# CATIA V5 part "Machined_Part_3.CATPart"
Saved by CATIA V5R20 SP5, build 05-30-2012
Part number: Machined_Part_3
Bounding box of the stored display mesh (mm): x -34.455 to 82.805, y -95.042 to 170.526, z 0 to 76.2
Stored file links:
  C:\Users\rsz0866\Documents\007_CATIA_STEP-Files_and_Test_Models\0001_Machined_Parts_Models\Machined_Part_3.CATPart
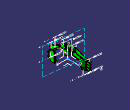
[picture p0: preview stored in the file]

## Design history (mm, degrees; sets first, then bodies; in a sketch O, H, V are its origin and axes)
AxisSystem1: origin (0, 0, 0), X (1, 0, 0), Y (0, 1, 0), Z (0, 0, 1)
AxisSystem2 "Axis System.2 ( *AXS1 - wsp *MASTER -  )": origin (0, 0, 0), X (1, 0, 0), Y (0, 1, 0), Z (0, 0, 1)
TTRSSet1
f4a2d38f3ddc11d3a929006094b99c4b_11 "CATTPSSet"
Set1
  Sketch1 "Top Sketch" on Plane12, origin (0, 0, 76.2), H (1, 0, 0), V (0, 1, 0)
    point P41 (38.3585, -78.4326)
    point P43 (38.3585, -78.4326)
    point P49 (-34.4551, -32.537)
    line L1 (77.9773, -17.6115) -> (82.8051, -65.2862)
    line L2 (45.9027, -87.2055) -> (51.7305, -93.9824)
    line L3 (37.3928, -77.3097) -> (13.1457, -49.1136)
    line L4 (6.9462, -45.7536) -> (-27.9108, -41.0986)
    line L5 (-8.3082, 163.2539) -> (-34.4551, -32.537)
    point P65 (-34.4551, -32.537)
    line L6 (3.5734, 151.0017) -> (3.0896, 147.3794)
    line L7 (8.4368, 108.2691) -> (1.2721, 54.6193)
    line L8 (53.3982, -33.8045) -> (32.3321, -30.9912)
    point P66 (53.3982, -33.8045)
    line L9 (53.6147, -32.2958) -> (53.3982, -33.8045)
    line L10 (43.6543, -82.0898) -> (45.4804, -86.5178)
    arc A1 centre (47.8285, -85.5494) radius 2.54 from (45.4804, -86.5178) to (45.9027, -87.2055) ccw
    arc A2 centre (0, 162.1444) radius 8.382 from (8.3082, 161.0349) to (-8.3082, 163.2539) ccw
    arc A3 centre (0, 162.1444) radius 8.382 from (6.1381, 156.4364) to (8.3082, 161.0349) ccw
    arc A4 centre (13.3922, 149.6905) radius 9.906 from (6.1381, 156.4364) to (3.5734, 151.0017) ccw
    arc A5 centre (12.908, 146.0685) radius 9.9055 from (3.0896, 147.3794) to (3.9015, 141.9453) ccw
    arc A6 centre (12.9085, 146.0686) radius 9.906 from (3.9015, 141.9453) to (11.4699, 136.2676) ccw
    arc A7 centre (10.0681, 126.7179) radius 9.652 from (14.2492, 118.0186) to (13.094, 135.8834) ccw
    arc A8 centre (10.0681, 126.7179) radius 9.652 from (13.094, 135.8834) to (11.4699, 136.2676) ccw
    arc A9 centre (18.5404, 109.0903) radius 9.906 from (14.2492, 118.0186) to (9.5986, 113.3534) ccw
    arc A10 centre (18.5396, 109.0905) radius 9.9052 from (9.5986, 113.3534) to (8.7216, 110.4015) ccw
    line L11 (8.7216, 110.4015) -> (8.4368, 108.2691)
    arc A11 centre (11.091, 53.308) radius 9.906 from (1.2721, 54.6193) to (2.0839, 49.1847) ccw
    arc A12 centre (11.091, 53.308) radius 9.906 from (2.0839, 49.1847) to (8.555, 43.7321) ccw
    arc A13 centre (6.9294, 37.5937) radius 6.35 from (12.9966, 35.7199) to (8.555, 43.7321) ccw
    arc A14 centre (22.4615, 32.7967) radius 9.906 from (12.9966, 35.7199) to (13.6686, 28.2344) ccw
    arc A15 centre (22.4611, 32.7964) radius 9.9055 from (13.6686, 28.2344) to (16.8641, 24.6237) ccw
    arc A16 centre (0, 0) radius 29.845 from (25.2594, -15.8962) to (16.8641, 24.6237) ccw
    arc A17 centre (33.6433, -21.1723) radius 9.906 from (25.2594, -15.8962) to (32.3321, -30.9912) ccw
    arc A18 centre (79.7726, -65.5933) radius 3.048 from (79.2019, -68.5874) to (82.8051, -65.2862) ccw
    arc A19 centre (75.6351, -87.3005) radius 19.05 from (79.2019, -68.5874) to (57.0199, -91.3476) ccw
    arc A20 centre (54.0415, -91.9951) radius 3.048 from (51.7305, -93.9824) to (57.0199, -91.3476) ccw
    construction arc A21 centre (47.9877, -70.152) radius 12.7 from (38.3585, -78.4326) to (46.7838, -82.7948) ccw
    arc A22 centre (47.9877, -70.152) radius 12.7 from (38.3585, -78.4326) to (43.6543, -82.0898) ccw
    line L12 (38.3585, -78.4326) -> (37.3928, -77.3097)
    arc A23 centre (5.6352, -55.5721) radius 9.9056 from (13.1457, -49.1136) to (8.548, -46.1045) ccw
    arc A24 centre (5.6349, -55.5724) radius 9.906 from (8.548, -46.1045) to (6.9462, -45.7536) ccw
    arc A25 centre (-26.9022, -33.5457) radius 7.62 from (-34.4551, -32.537) to (-27.9108, -41.0986) ccw
    line L13 (53.6147, -32.2958) -> (54.0504, -29.2591)
    line L14 (54.2639, -27.7708) -> (54.0504, -29.2591)
    line L15 (54.2639, -27.7708) -> (60.1112, -16.8496)
    arc A26 centre (64.3366, -25.5275) radius 9.652 from (65.6142, -15.9605) to (60.1112, -16.8496) ccw
    line L16 (74.3541, -17.1276) -> (65.6142, -15.9605)
    line L17 (74.3541, -17.1276) -> (75.9069, -17.335)
    line L18 (75.9069, -17.335) -> (77.9773, -17.6115)
    construction line L19 (39.3447, -71.6399) -> (45.4804, -86.5178)
    radius A1 = 2.54
    tangency: L1 A18, L2 A20, L3 A20, L4 A25, L5 A2, L6 A4, L7 A11, L8 A17, A1 L10, A1 L2
    coincidence: P66 L13, L10 L19, P41 P43, P49 P65
    parallelism: L9 L13
  Sketch2 "Cut 1 Sketch" on Plane13, origin (0, 0, 5.08), H (1, 0, 0), V (0, 1, 0)
    point P2 (4.1097, 119.1239)
    point P4 (4.1097, 119.1239)
    line L1 (3.0897, 147.3797) -> (0.52, 128.1375)
    line L2 (3.0897, 147.3797) -> (33.2265, 145.3887)
    line L3 (31.6407, 108.2613) -> (8.4357, 108.2613)
    line L4 (33.2265, 145.3887) -> (31.6407, 108.2613)
    construction arc A1 centre (-3.3972, 109.8415) radius 11.938 from (8.4357, 108.2613) to (4.1097, 119.1239) ccw
    arc A2 centre (-3.3972, 109.8415) radius 11.938 from (8.4357, 108.2613) to (4.1097, 119.1239) ccw
    arc A3 centre (10.3388, 126.8263) radius 9.906 from (0.52, 128.1375) to (4.1097, 119.1239) ccw
    coincidence: P2 P4
    horizontal: L3 H
  Sketch3 "Cut 2 Sketch" on Plane17, origin (0, 0, 67.3735), H (1, 0, 0), V (0, 1, 0)
    arc A1 centre (11.0905, 53.3079) radius 9.9056 from (1.2721, 54.6193) to (2.0839, 49.1847) ccw
    arc A2 centre (11.091, 53.308) radius 9.906 from (2.0839, 49.1847) to (8.555, 43.7321) ccw
    arc A3 centre (6.9294, 37.5937) radius 6.35 from (12.9966, 35.7199) to (8.555, 43.7321) ccw
    arc A4 centre (22.4615, 32.7967) radius 9.906 from (12.9966, 35.7199) to (13.6686, 28.2344) ccw
    arc A5 centre (22.4611, 32.7964) radius 9.9055 from (13.6686, 28.2344) to (16.8641, 24.6237) ccw
    arc A6 centre (0, 0) radius 29.845 from (16.8641, 24.6237) to (6.861, 29.0457) ccw
    arc A7 centre (9.1383, 38.6863) radius 9.906 from (-0.6805, 39.9976) to (5.9121, 29.3204) ccw
    line L1 (1.2721, 54.6193) -> (-0.6805, 39.9976)
    arc A8 centre (9.1383, 38.6863) radius 9.906 from (5.9121, 29.3204) to (6.861, 29.0457) ccw
  Sketch4 "Pocket 1 Sketch" on Plane11, origin (0, 0, 59.4614), H (1, 0, 0), V (0, 1, 0)
    point P4 (-3.2329, 36.236)
    point P7 (-22.8706, 38.8585)
    line L1 (-13.216, 111.1528) -> (-22.8706, 38.8585)
    point P9 (-22.8706, 38.8585)
    line L2 (6.4216, 108.5303) -> (-3.2329, 36.236)
    point P10 (-3.2329, 36.236)
    arc A1 centre (-3.3972, 109.8415) radius 9.906 from (6.4216, 108.5303) to (-13.216, 111.1528) ccw
    arc A2 centre (-13.0517, 37.5472) radius 9.906 from (-5.7297, 30.8751) to (-3.2329, 36.236) ccw
    arc A3 centre (-13.0517, 37.5472) radius 9.906 from (-21.868, 33.0303) to (-5.7297, 30.8751) ccw
    arc A4 centre (-13.0517, 37.5472) radius 9.906 from (-22.8706, 38.8585) to (-21.868, 33.0303) ccw
    coincidence: P9 A4, P4 P10, P7 P9
    tangency: L1 A2, L2 A1
  Sketch5 "Step 1 Sketch" on Plane20, origin (0, 0, 67.3735), H (1, 0, 0), V (0, 1, 0)
    arc A1 centre (5.6352, -55.5721) radius 9.9056 from (13.1457, -49.1136) to (8.548, -46.1045) ccw
    line L1 (13.1457, -49.1136) -> (6.9025, -41.8536)
    line L2 (-1.3126, -32.3005) -> (6.9025, -41.8536)
    arc A2 centre (-8.8234, -38.7594) radius 9.906 from (-1.3126, -32.3005) to (-6.6246, -29.1005) ccw
    arc A3 centre (0, 0) radius 29.845 from (-10.6775, -27.8696) to (-6.6246, -29.1005) ccw
    line L3 (-10.6775, -27.8696) -> (-22.6141, -23.2964)
    arc A4 centre (-26.1581, -32.5468) radius 9.906 from (-22.6141, -23.2964) to (-24.8468, -22.7279) ccw
    line L4 (-24.8468, -22.7279) -> (-30.4821, -21.9754)
    arc A5 centre (-30.1459, -19.4577) radius 2.54 from (-32.6635, -19.1215) to (-30.4821, -21.9754) ccw
    line L5 (-33.0835, -22.266) -> (-32.6635, -19.1215)
    line L6 (-34.4551, -32.537) -> (-33.0835, -22.266)
    arc A6 centre (-26.9022, -33.5457) radius 7.62 from (-34.4551, -32.537) to (-27.9108, -41.0986) ccw
    line L7 (-19.0026, -42.2883) -> (-27.9108, -41.0986)
    line L8 (-19.0026, -42.2883) -> (-17.492, -42.49)
    line L9 (6.9462, -45.7536) -> (-17.492, -42.49)
    arc A7 centre (5.6349, -55.5724) radius 9.906 from (8.548, -46.1045) to (6.9462, -45.7536) ccw
  Sketch6 "Cut 3 Sketch" on Plane26, origin (0, 0, 6.858), H (1, 0, 0), V (0, 1, 0)
    line L1 (-19.0026, -42.2883) -> (-27.9108, -41.0986)
    arc A1 centre (-26.9022, -33.5457) radius 7.62 from (-34.4551, -32.537) to (-27.9108, -41.0986) ccw
    line L2 (-34.4551, -32.537) -> (-33.0835, -22.266)
    line L3 (-33.0835, -22.266) -> (-32.6635, -19.1215)
    arc A2 centre (-30.1459, -19.4577) radius 2.54 from (-32.6635, -19.1215) to (-30.4821, -21.9754) ccw
    line L4 (-24.8468, -22.7279) -> (-30.4821, -21.9754)
    arc A3 centre (-26.1581, -32.5468) radius 9.906 from (-22.6141, -23.2964) to (-24.8468, -22.7279) ccw
    arc A4 centre (-26.1576, -32.5461) radius 9.9052 from (-18.2294, -26.6083) to (-22.6141, -23.2964) ccw
    arc A5 centre (-26.1581, -32.5468) radius 9.906 from (-16.3393, -33.858) to (-18.2294, -26.6083) ccw
    line L5 (-17.492, -42.49) -> (-16.3393, -33.858)
    line L6 (-19.0026, -42.2883) -> (-17.492, -42.49)
  Sketch7 "Step 2 Sketch" on Plane22, origin (0, 0, 67.3735), H (1, 0, 0), V (0, 1, 0)
    line L1 (78.9049, -46.9405) -> (83.4372, -91.6975)
    line L2 (14.7318, -48.1756) -> (63.5889, -104.4908)
    line L3 (63.5889, -104.4908) -> (83.4372, -91.6975)
    arc A1 centre (69.0493, -47.9386) radius 9.906 from (78.9049, -46.9405) to (70.3606, -38.1197) ccw
    line L4 (23.5256, -31.8652) -> (70.3606, -38.1197)
    arc A2 centre (22.2143, -41.684) radius 9.906 from (23.5256, -31.8652) to (15.7227, -34.2015) ccw
    arc A3 centre (22.2143, -41.684) radius 9.906 from (15.7228, -34.2014) to (14.7318, -48.1756) ccw
    tangency: L1 A1, L2 A3
  Sketch8 "Cut 4 Sketch" on Plane18, origin (0, 0, 5.08), H (1, 0, 0), V (0, 1, 0)
    point P1 (65.4758, -35.4173)
    point P15 (53.6147, -32.2958)
    point P17 (53.6147, -32.2958)
    point P20 (65.4758, -35.4173)
    arc A1 centre (66.787, -25.5985) radius 9.906 from (65.4758, -35.4173) to (76.6426, -24.6005) ccw
    line L1 (76.6426, -24.6005) -> (75.9069, -17.335)
    line L2 (74.3541, -17.1276) -> (65.6142, -15.9605)
    arc A2 centre (64.3366, -25.5275) radius 9.652 from (65.6142, -15.9605) to (60.1112, -16.8496) ccw
    line L3 (54.2639, -27.7708) -> (60.1112, -16.8496)
    line L4 (74.3541, -17.1276) -> (75.9069, -17.335)
    line L5 (54.2639, -27.7708) -> (54.0504, -29.2591)
    line L6 (53.6147, -32.2958) -> (54.0504, -29.2591)
    construction line L7 (53.6147, -32.2958) -> (53.3982, -33.8045)
    line L8 (53.6147, -32.2958) -> (53.3982, -33.8045)
    construction line L9 (52.5433, -33.6903) -> (65.4758, -35.4173)
    line L10 (53.3982, -33.8045) -> (65.4758, -35.4173)
    coincidence: P1 P20, P15 P17
  Sketch9 "Side 1 Sketch" on Plane14, origin (-29.5824, 3.9506, 0), H (-0.1324, -0.9912, 0), V (0, 0, 1)
    point P8 (18.4332, 0)
    point P17 (18.4332, 0)
    line L1 (18.4332, 0) -> (18.4332, -23.6301)
    line L2 (18.4332, -23.6301) -> (-108.4253, -23.6301)
    line L3 (-108.4253, -23.6301) -> (-108.4253, 0)
    arc A1 centre (5.7049, 53.8766) radius 2.286 from (7.9494, 54.3099) to (5.7049, 56.1626) ccw
    line L4 (5.7049, 56.1626) -> (-9.5351, 56.1626)
    arc A2 centre (-9.5351, 53.8766) radius 2.286 from (-9.5351, 56.1626) to (-11.1593, 55.4853) ccw
    line L5 (7.9494, 54.3099) -> (18.4332, 0)
    line L6 (-11.1593, 55.4853) -> (-26.0895, 40.4114)
    line L7 (-26.0895, 40.4114) -> (-83.7739, 40.4114)
    arc A3 centre (-83.7739, 38.1254) radius 2.286 from (-83.7739, 40.4114) to (-85.7536, 39.2684) ccw
    line L8 (-108.4253, 0) -> (-85.7536, 39.2684)
    coincidence: P17 H, P8 P17
    vertical: L1 V, L3 V
    horizontal: L2 H
  Sketch10 "Cut 5 Sketch" on Plane14, origin (-29.5824, 3.9506, 0), H (-0.1324, -0.9912, 0), V (0, 0, 1)
    line L1 (-135.0636, 56.1594) -> (-183.8689, 56.1594)
    line L2 (-135.0636, 42.4434) -> (-183.8689, 42.4434)
    line L3 (-135.0636, 25.4254) -> (-185.0407, 25.4254)
    line L4 (-135.0636, 22.1234) -> (-185.6717, 22.1234)
    line L5 (-135.0636, 8.4074) -> (-185.6717, 8.4074)
    line L6 (-146.4936, 5.1054) -> (-185.0407, 5.1054)
    line L7 (-144.9696, 0) -> (-185.0407, 0)
    line L8 (-183.8689, 56.1594) -> (-183.8689, 42.4434)
    line L9 (-135.0636, 39.1414) -> (-185.0407, 39.1414)
    line L10 (-185.0407, 39.1414) -> (-185.0407, 25.4254)
    line L11 (-185.6717, 8.4074) -> (-185.6717, 22.1234)
    line L12 (-185.0407, 5.1054) -> (-185.0407, 0)
    arc A1 centre (-135.0636, 54.6354) radius 1.524 from (-133.5396, 54.6354) to (-135.0636, 56.1594) ccw
    arc A2 centre (-135.0636, 43.9674) radius 1.524 from (-135.0636, 42.4434) to (-133.5396, 43.9674) ccw
    line L13 (-133.5396, 43.9674) -> (-133.5396, 54.6354)
    arc A3 centre (-135.0636, 37.6174) radius 1.524 from (-133.5396, 37.6174) to (-135.0636, 39.1414) ccw
    line L14 (-133.5396, 26.9494) -> (-133.5396, 37.6174)
    arc A4 centre (-135.0636, 26.9494) radius 1.524 from (-135.0636, 25.4254) to (-133.5396, 26.9494) ccw
    arc A5 centre (-135.0636, 20.5994) radius 1.524 from (-133.5396, 20.5994) to (-135.0636, 22.1234) ccw
    line L15 (-133.5396, 9.9314) -> (-133.5396, 20.5994)
    arc A6 centre (-135.0636, 9.9314) radius 1.524 from (-135.0636, 8.4074) to (-133.5396, 9.9314) ccw
    arc A7 centre (-146.4936, 3.5814) radius 1.524 from (-144.9696, 3.5814) to (-146.4936, 5.1054) ccw
    line L16 (-144.9696, 0) -> (-144.9696, 3.5814)
    tangency: L1 A1, L2 A2, L3 A4, L4 A5, L5 A6, L6 A7, L9 A3
    horizontal: L7 H
    vertical: L8 V, L10 V, L11 V, L12 V
  Sketch11 "Bump Sketch" on Plane15, origin (0, 0, 60.7314), H (1, 0, 0), V (0, 1, 0)
    line L1 (2.2134, 150.8948) -> (3.5355, 150.7183)
    line L2 (3.5355, 150.7183) -> (1.8544, 138.13)
    line L3 (1.8544, 138.13) -> (0.5323, 138.3066)
    line L4 (0.5323, 138.3066) -> (2.2134, 150.8948)
  Sketch12 "Cut 6 Sketch" on Plane14, origin (-29.5824, 3.9506, 0), H (-0.1324, -0.9912, 0), V (0, 0, 1)
    line L1 (-17.0582, 79.0477) -> (-104.731, 59.5221)
    line L2 (-105.2832, 59.4614) -> (-175.7026, 59.4614)
    line L3 (-175.7026, 59.4614) -> (-175.7026, 79.0477)
    line L4 (-17.0582, 79.0477) -> (-175.7026, 79.0477)
    arc A1 centre (-105.2832, 62.0014) radius 2.54 from (-104.731, 59.5221) to (-105.2832, 59.4614) cw
    construction line L5 (-29.845, 76.2) -> (-104.7583, 59.5161)
    construction line L6 (-105.2553, 59.4614) -> (-160.7176, 59.4614)
    radius A1 = 2.54
    horizontal: L2 H, L4 H
    vertical: L3 V
    coincidence: L5 L1, L6 L2
    tangency: A1 L1, A1 L2
  Sketch13 "Cut 7 Sketch" on Plane1, origin (79.0424, -10.5557, 0), H (0.1324, 0.9912, 0), V (0, 0, 1)
    line L1 (-27.499, 76.8669) -> (-40.6805, 67.8193)
    line L2 (-42.1179, 67.3735) -> (-64.6036, 67.3735)
    line L3 (-64.6036, 67.3735) -> (-64.6036, 76.8669)
    line L4 (-64.6036, 76.8669) -> (-27.499, 76.8669)
    arc A1 centre (-42.1179, 69.9135) radius 2.54 from (-40.6805, 67.8193) to (-42.1179, 67.3735) cw
    construction line L5 (-40.7455, 67.7748) -> (-28.4707, 76.2)
    construction line L6 (-50.6037, 67.3735) -> (-54.4936, 67.3735)
    radius A1 = 2.54
    horizontal: L2 H, L4 H
    vertical: L3 V
    coincidence: L1 L5, L2 L6
    tangency: A1 L1, A1 L2
  Sketch14 "Cut 8 Sketch" on Plane22, origin (0, 0, 67.3735), H (1, 0, 0), V (0, 1, 0)
    line L1 (81.7555, -54.9213) -> (100.4309, -60.408)
    line L2 (100.4309, -60.408) -> (51.4529, -106.5897)
    line L3 (51.4529, -106.5897) -> (38.3585, -78.4326)
    arc A1 centre (79.6916, -64.6396) radius 9.906 from (81.0029, -54.8208) to (78.1741, -54.8505) ccw
    arc A2 centre (79.6916, -64.6396) radius 9.906 from (78.1741, -54.8505) to (70.6949, -60.4939) ccw
    arc A3 centre (64.9277, -57.8364) radius 6.35 from (66.8132, -63.9) to (70.6949, -60.4939) ccw
    arc A4 centre (72.4698, -82.0908) radius 19.05 from (66.8132, -63.9) to (53.8878, -77.8941) ccw
    arc A5 centre (47.6938, -76.4952) radius 6.35 from (47.4, -82.8384) to (53.8878, -77.8941) ccw
    arc A6 centre (47.9877, -70.152) radius 12.7 from (46.7838, -82.7948) to (47.4, -82.8384) ccw
    arc A7 centre (47.9877, -70.152) radius 12.7 from (38.3585, -78.4326) to (46.7838, -82.7948) ccw
    line L4 (81.0029, -54.8208) -> (81.7555, -54.9213)
    tangency: L1 A1
  Sketch15 "Cut 9 Sketch" on Plane19, origin (0, 0, 24.4475), H (1, 0, 0), V (0, -1, 0)
    line L1 (25.2038, 73.626) -> (25.2038, 24.2643)
    line L2 (51.4054, 47.6939) -> (54.641, 24.2643)
    line L3 (54.641, 24.2643) -> (25.2038, 24.2643)
    line L4 (48.0914, 53.7696) -> (25.2038, 73.626)
    arc A1 centre (41.5998, 46.2871) radius 9.906 from (50.6156, 50.3913) to (48.0914, 53.7696) ccw
    arc A2 centre (41.6087, 46.2901) radius 9.8967 from (51.2246, 48.6307) to (50.6156, 50.3913) ccw
    arc A3 centre (41.5998, 46.2871) radius 9.906 from (51.4054, 47.6939) to (51.2246, 48.6307) ccw
    vertical: L1 V
    tangency: L2 A2, L4 A1
    horizontal: L3 H
  Sketch16 "Cut 10 Sketch" on Plane19, origin (0, 0, 24.4475), H (1, 0, 0), V (0, -1, 0)
    point P4 (55.098, 66.7637)
    point P12 (53.2843, 48.9058)
    point P13 (53.3376, 48.5343)
    line L1 (41.8105, 63.5221) -> (41.3894, 64.0584)
    line L2 (55.098, 66.7637) -> (60.2297, 72.3813)
    point P28 (55.098, 66.7637)
    line L3 (55.7365, 64.4498) -> (61.7651, 71.0493)
    line L4 (78.9049, 46.9405) -> (80.0245, 57.9963)
    line L5 (36.6639, 58.6116) -> (10.6615, 84.8174)
    line L6 (10.6615, 84.8174) -> (55.7365, 100.8474)
    line L7 (55.7365, 100.8474) -> (103.6523, 61.1517)
    line L8 (53.3376, 48.5343) -> (53.2843, 48.9058)
    point P36 (53.3376, 48.5343)
    arc A1 centre (45.7214, 75.3292) radius 12.7 from (42.5224, 63.0387) to (48.9088, 63.0357) ccw
    arc A2 centre (45.7214, 75.3292) radius 12.7 from (48.9088, 63.0357) to (55.098, 66.7637) ccw
    arc A3 centre (65.1131, 55.8843) radius 12.7 from (55.7365, 64.4498) to (52.9481, 59.5314) ccw
    arc A4 centre (65.1131, 55.8843) radius 12.7 from (52.9481, 59.5314) to (52.5419, 54.0806) ccw
    line L9 (52.5419, 54.0806) -> (53.025, 50.713)
    line L10 (53.025, 50.713) -> (53.2843, 48.9058)
    arc A5 centre (65.9089, 50.338) radius 12.7 from (53.3376, 48.5343) to (67.59, 37.7497) ccw
    line L11 (67.59, 37.7497) -> (70.3606, 38.1197)
    arc A6 centre (69.0493, 47.9386) radius 9.906 from (70.3606, 38.1197) to (78.9049, 46.9405) ccw
    frozenspline C1
    construction line L12 through (-8.0936, 7.0217) direction (-0.6553, -0.7554)
    line L13 (41.3894, 64.0584) -> (36.6639, 58.6116)
    construction line L14 through (61.6936, 71.1113) direction (0.7554, -0.6553)
    line L15 (60.2297, 72.3813) -> (61.7651, 71.0493)
    construction line L16 through (-6.2072, 46.4806) direction (-0.9912, -0.1324)
    line L17 (103.6523, 61.1517) -> (80.0245, 57.9963)
    coincidence: L1 P12, P28 A2, P36 A5, P36 L10, P4 P28, P13 P36
    tangency: L2 A1, L3 A3, L4 A6, L8 A5
  Sketch17 "Cut 11 Sketch" on Plane6, origin (83.9556, -11.2118, 0), H (0.1324, 0.9912, 0), V (0, 0, 1)
    line L1 (-46.2073, 23.5372) -> (-23.2619, -6.9123)
    point P3 (-23.2619, -6.9123)
    line L2 (-48.033, 24.4475) -> (-70.3017, 24.4475)
    line L3 (-23.2619, -6.9123) -> (-70.3017, -6.9123)
    point P5 (-23.2619, -6.9123)
    line L4 (-70.3017, -6.9123) -> (-70.3017, 24.4475)
    arc A1 centre (-48.033, 22.1615) radius 2.286 from (-46.2073, 23.5372) to (-48.033, 24.4475) ccw
    tangency: L1 A1, L2 A1
    coincidence: P5 L1, P3 P5
    horizontal: L3 H
    vertical: L4 V
  Sketch18 on Plane6, origin (83.9556, -11.2118, 0), H (0.1324, 0.9912, 0), V (0, 0, 1)
    line L1 (-41.4222, 17.1872) -> (-25.7258, -3.6425)
    point P3 (-25.7258, -3.6425)
    line L2 (-43.2479, 18.0975) -> (-68.5047, 18.0975)
    line L3 (-68.5047, -3.6425) -> (-25.7258, -3.6425)
    point P5 (-25.7258, -3.6425)
    line L4 (-68.5047, -3.6425) -> (-68.5047, 18.0975)
    arc A1 centre (-43.2479, 15.8115) radius 2.286 from (-41.4222, 17.1872) to (-43.2479, 18.0975) ccw
    tangency: L1 A1, L2 A1
    coincidence: P5 L1, P3 P5
    vertical: L4 V
  Sketch19 on Plane7, origin (49.7371, -57.3295, 0), H (0.7554, 0.6553, 0), V (0, 0, 1)
    point P1 (-10.0454, 23.7779)
    line L1 (-10.0454, 23.7779) -> (-1.6921, 15.4247)
    point P3 (-10.0454, 23.7779)
    line L2 (-1.6921, 15.4247) -> (-17.8508, 15.4247)
    line L3 (-17.8508, 24.4475) -> (-11.6619, 24.4475)
    line L4 (-17.8508, 24.4475) -> (-17.8508, 15.4247)
    arc A1 centre (-11.6619, 22.1615) radius 2.286 from (-10.0454, 23.7779) to (-11.6619, 24.4475) ccw
    coincidence: P3 A1, P1 P3
    tangency: L1 A1, L3 A1
    horizontal: L2 H
    vertical: L4 V
  Sketch20 on Plane8, origin (-1.2775, -1.1083, 0), H (-0.6553, 0.7554, 0), V (0, 0, 1)
    line L1 (-110.9211, 24.4475) -> (-94.1431, 24.4475)
    line L2 (-94.1431, 24.4475) -> (-75.1591, 16.1212)
    line L3 (-75.1591, 16.1212) -> (-110.9211, 16.1212)
    line L4 (-110.9211, 16.1212) -> (-110.9211, 24.4475)
    construction line L5 (-104.8899, 24.4475) -> (-95.9518, 24.4475)
    construction line L6 (-90.6684, 22.9235) -> (-86.5369, 21.1115)
    horizontal: L1 H, L3 H
    vertical: L4 V
    coincidence: L1 L5, L2 L6
  Sketch21 on Plane9, origin (-16.7791, -14.5569, 0), H (0.6553, -0.7554, 0), V (0, 0, 1)
    line L1 (82.9003, 67.3735) -> (118.8045, 67.3735)
    line L2 (82.4744, 67.4135) -> (22.7115, 78.7459)
    line L3 (118.8045, 67.3735) -> (118.8045, 78.7459)
    line L4 (118.8045, 78.7459) -> (22.7115, 78.7459)
    arc A1 centre (82.9003, 69.6595) radius 2.286 from (82.4744, 67.4135) to (82.9003, 67.3735) ccw
    tangency: L1 A1, L2 A1
    vertical: L3 V
    horizontal: L4 H
  Sketch22 on Plane16, origin (0, 0, 40.4114), H (1, 0, 0), V (0, -1, 0)
    line L1 (6.4216, -108.5303) -> (2.3867, -78.3161)
    line L2 (-13.216, -111.1528) -> (-17.1757, -81.5021)
    line L3 (-17.1757, -81.5021) -> (2.3867, -78.3161)
    arc A1 centre (-3.3972, -109.8415) radius 9.906 from (-13.216, -111.1528) to (6.4216, -108.5303) ccw
    tangency: L1 A1, L2 A1
  Sketch23 on Plane21, origin (0, 0, 65.3415), H (1, 0, 0), V (0, -1, 0)
    line L1 (52.5433, 33.6903) -> (64.5759, -46.1654)
    line L2 (1.2721, -54.6193) -> (64.5759, -46.1654)
    line L3 (45.4804, 86.5178) -> (-15.4779, 42.759)
    line L4 (1.2721, -54.6193) -> (-1.2188, -35.967)
    arc A1 centre (-13.0517, -37.5472) radius 11.938 from (-1.2188, -35.967) to (-7.0013, -27.2561) ccw
    arc A2 centre (-13.0517, -37.5472) radius 11.938 from (-7.0013, -27.2561) to (-9.132, -26.2711) ccw
    arc A3 centre (0, 0) radius 27.813 from (-23.7748, -14.4334) to (-9.132, -26.2711) ccw
    arc A4 centre (-0.0731, -0.0413) radius 27.7291 from (-24.6354, -12.9097) to (-23.7748, -14.4334) ccw
    arc A5 centre (0, 0) radius 27.813 from (-27.5683, -3.6816) to (-24.6354, -12.9097) ccw
    line L5 (-28.3234, 1.9731) -> (-27.5683, -3.6816)
    line L6 (-28.6205, 4.1979) -> (-28.3234, 1.9731)
    line L7 (-28.6205, 4.1979) -> (-28.919, 6.4329)
    arc A6 centre (-19.1002, 7.7442) radius 9.906 from (-25.6558, 15.1707) to (-28.919, 6.4329) ccw
    line L8 (-17.2201, 21.8411) -> (-25.2333, 15.5232)
    arc A7 centre (0, 0) radius 27.813 from (-14.4704, 23.7523) to (-17.2201, 21.8411) ccw
    arc A8 centre (-15.7919, 25.9214) radius 2.54 from (-14.4704, 23.7523) to (-13.2742, 26.2577) ccw
    line L9 (-13.2742, 26.2577) -> (-15.4779, 42.759)
    arc A9 centre (41.4788, 27.4553) radius 12.7003 from (52.5433, 33.6903) to (51.6851, 35.0137) ccw
    arc A10 centre (41.4791, 27.4554) radius 12.7 from (51.6851, 35.0137) to (44.8545, 39.6987) ccw
    arc A11 centre (46.8798, 47.0446) radius 7.62 from (39.3268, 46.0359) to (44.8545, 39.6987) ccw
    line L10 (39.3268, 46.0359) -> (37.6498, 58.5938)
    arc A12 centre (62.8263, 61.956) radius 25.4 from (37.9834, 67.2467) to (37.4447, 60.9887) ccw
    arc A13 centre (62.8263, 61.956) radius 25.4 from (37.4447, 60.9887) to (37.6498, 58.5938) ccw
    arc A14 centre (62.8263, 61.956) radius 25.4 from (39.3447, 71.6399) to (37.9834, 67.2467) ccw
    line L11 (45.4804, 86.5178) -> (39.3447, 71.6399)
    perpendicularity: L2 L4
  Sketch24 on Plane34, origin (90.0787, 7.4041, 0), H (0.1324, 0.9912, 0), V (0, 0, 1)
    point P2 (-62.8786, 41.9735)
    point P3 (-62.8786, 41.9735)
    line L1 (-62.8786, 26.4795) -> (-103.3566, 26.4795)
    line L2 (-103.3566, 26.4795) -> (-103.3566, 65.3415)
    line L3 (-103.3566, 65.3415) -> (-62.8786, 65.3415)
    construction line L4 (-62.8786, 67.3735) -> (-62.8786, 41.9735)
    line L5 (-62.8786, 65.3415) -> (-62.8786, 41.9735)
    construction line L6 (-62.8786, 41.9735) -> (-62.8786, 28.0035)
    line L7 (-62.8786, 41.9735) -> (-62.8786, 26.4795)
    construction line L8 (-89.3381, 65.3415) -> (-73.7562, 65.3415)
    horizontal: L1 H, L3 H
    vertical: L2 V
    coincidence: L3 L8, P2 P3
  Sketch25 on Plane23, origin (-3.4997, -26.206, 0), H (-0.9912, 0.1324, 0), V (0, 0, 1)
    line L1 (-60.5746, 65.3415) -> (-38.49, 65.3417)
    line L2 (-38.49, 65.3417) -> (-38.49, 26.4794)
    line L3 (-38.49, 26.4794) -> (-60.5746, 26.4794)
    arc A1 centre (-60.5746, 36.3854) radius 9.906 from (-69.5878, 32.2755) to (-60.5746, 26.4794) ccw
    arc A2 centre (-60.5746, 36.3855) radius 9.9061 from (-70.4806, 36.3855) to (-69.5878, 32.2755) ccw
    line L4 (-70.4806, 55.4355) -> (-70.4806, 36.3855)
    arc A3 centre (-60.5746, 55.4355) radius 9.906 from (-69.5878, 59.5455) to (-70.4806, 55.4355) ccw
    arc A4 centre (-60.5746, 55.4355) radius 9.906 from (-60.5746, 65.3415) to (-69.5878, 59.5455) ccw
    tangency: L1 A3, L3 A1
    vertical: L2 V
  Sketch26 on Plane25, origin (-4.1804, -31.3037, 0), H (0.9912, -0.1324, 0), V (0, 0, 1)
    point P1 (81.9953, 55.4355)
    point P4 (74.9483, 26.9011)
    point P7 (63.7244, 65.3415)
    point P9 (63.7244, 65.3415)
    point P12 (48.403, 65.3415)
    point P13 (48.403, 65.3415)
    point P18 (63.7157, 26.4795)
    point P19 (63.7157, 26.4795)
    line L1 (45.0745, 26.4795) -> (45.0745, 65.3415)
    arc A1 centre (72.0893, 55.4355) radius 9.906 from (81.9953, 55.4355) to (72.0893, 65.3415) ccw
    arc A2 centre (72.0892, 36.3857) radius 9.9062 from (72.0892, 26.4795) to (81.9953, 36.3857) ccw
    construction line L2 (81.9953, 55.4355) -> (81.9953, 36.3855)
    line L3 (81.9953, 55.4355) -> (81.9953, 36.3857)
    construction arc A3 centre (72.0896, 36.3831) radius 9.9036 from (72.0893, 26.4795) to (74.9483, 26.9011) ccw
    construction arc A4 centre (72.0896, 55.4379) radius 9.9036 from (74.9487, 64.9198) to (72.0893, 65.3415) ccw
    construction line L4 (63.7244, 65.3415) -> (74.6837, 65.3415)
    line L5 (63.7244, 65.3415) -> (72.0893, 65.3415)
    line L6 (63.7244, 65.3415) -> (57.9482, 65.3415)
    line L7 (57.9482, 65.3415) -> (48.403, 65.3415)
    construction line L8 (48.403, 65.3415) -> (19.5312, 65.3415)
    line L9 (48.403, 65.3415) -> (45.0745, 65.3415)
    construction line L10 (67.4754, 26.4795) -> (87.5838, 26.4795)
    construction line L11 (68.7913, 26.4795) -> (63.7157, 26.4795)
    line L12 (72.0892, 26.4795) -> (63.7157, 26.4795)
    line L13 (63.7157, 26.4795) -> (57.0421, 26.4795)
    line L14 (57.0421, 26.4795) -> (56.5325, 26.4795)
    line L15 (48.4814, 26.4795) -> (56.5325, 26.4795)
    line L16 (48.4814, 26.4795) -> (45.0745, 26.4795)
    vertical: L1 V
    coincidence: P7 P9, P12 P13, P18 P19, A1 P1, A2 P4
    tangency: A1 L2, A2 L2
  Sketch27 on Plane24, origin (-5.0155, -37.5568, 0), H (0.9912, -0.1324, 0), V (0, 0, 1)
    arc A1 centre (74.9483, 55.4355) radius 9.906 from (84.8543, 55.4355) to (74.9483, 65.3415) ccw
    arc A2 centre (74.9483, 36.3855) radius 9.906 from (74.9483, 26.4795) to (84.8543, 36.3855) ccw
    line L1 (74.9483, 65.3415) -> (56.3643, 65.3415)
    line L2 (74.9483, 26.4795) -> (56.3643, 26.4795)
    line L3 (56.3643, 26.4795) -> (56.3643, 65.3415)
    line L4 (84.8543, 55.4355) -> (84.8543, 36.3855)
    tangency: L1 A1, L2 A2, L4 A1, A2 L4
    vertical: L3 V
  Sketch28 on Plane10, origin (0, 0, 0), H (0.941, -0.3384, 0), V (0, 0, 1)
    line L1 (-22.225, 76.2) -> (0, 76.2)
    point P15 (0, 76.2)
    line L2 (-25.1269, 65.3415) -> (0, 65.3415)
    point P16 (0, 65.3415)
    line L3 (-25.1269, 65.3415) -> (-24.619, 65.8495)
    line L4 (-24.6189, 65.8495) -> (-24.6189, 72.5282)
    line L5 (-24.6189, 72.5282) -> (-25.0662, 73.4874)
    arc A1 centre (-24.2605, 73.8631) radius 0.889 from (-23.9007, 74.676) to (-25.0662, 73.4874) ccw
    axis line L6 through (-21.7836, 0) direction (0, -1)
    line L7 (-22.225, 74.676) -> (-23.9007, 74.676)
    line L8 (-22.225, 74.676) -> (-22.225, 76.2)
    coincidence: P15 V, P16 V
    horizontal: L1 H, L2 H
Set2 "extra"
  Plane1 to Plane5: stored without definition
  Line1 to Line3: stored without definition
  Plane6 to Plane9: stored without definition
  Point1: stored without definition
  Plane10: stored without definition
  Line4: stored without definition
  Line5: stored without definition
  Circle1: stored without definition
  Line6 to Line12: stored without definition
  DatumCurve1
  Line13 to Line18: stored without definition
  Plane11 to Plane28: stored without definition
Set3
  Line19 "Line.1 ( *LN638 - wsp *MASTER -  )": stored without definition
  Line20 "Line.2 ( *LN641 - wsp *MASTER -  )": stored without definition
  Line21 "Line.3 ( *LN1535 - wsp *MASTER -  )": stored without definition
  Line22 "Line.4 ( *LN1536 - wsp *MASTER -  )": stored without definition
  Line23 "Line.5 ( *LN1537 - wsp *MASTER -  )": stored without definition
  Line24 "Line.6 ( *LN1744 - wsp *MASTER -  )": stored without definition
  Line25 "Line.7 ( *LN1819 - wsp *MASTER -  )": stored without definition
  Line26 "Line.8 ( *LN1820 - wsp *MASTER -  )": stored without definition
  Line27 "Line.9 ( *LN1821 - wsp *MASTER -  )": stored without definition
  Line28 "Line.10 ( *LN1837 - wsp *MASTER -  )": stored without definition
  Line29 "Line.11 ( *LN1890 - wsp *MASTER -  )": stored without definition
  Line30 "Line.12 ( *LN1891 - wsp *MASTER -  )": stored without definition
  Line31 "Line.13 ( *LN1924 - wsp *MASTER -  )": stored without definition
  Line32 "Line.14 ( *LN1925 - wsp *MASTER -  )": stored without definition
  Line33 "Line.15 ( *LN1939 - wsp *MASTER -  )": stored without definition
  Line34 "Line.16 ( *LN1940 - wsp *MASTER -  )": stored without definition
  Line35 "Line.17 ( *LN2040 - wsp *MASTER -  )": stored without definition
  Plane29 "Plane.1 ( DATUM A - wsp *MASTER -  )": stored without definition
  Point2 "Point.1 ( DATUM B - wsp *MASTER -  )": stored without definition
  Point3 "Point.2 ( DATUM C - wsp *MASTER -  )": stored without definition
  Point4 "Point.3 ( *PT1 - wsp *MASTER -  )": stored without definition
  Point5 "Point.4 ( *PT2 - wsp *MASTER -  )": stored without definition
  Point6 "Point.5 ( *PT3 - wsp *MASTER -  )": stored without definition
  Point7 "Point.6 ( *PT4 - wsp *MASTER -  )": stored without definition
  Point8 "Point.7 ( *PT5 - wsp *MASTER -  )": stored without definition
  Point9 "Point.8 ( *PT6 - wsp *MASTER -  )": stored without definition
  Point10 "Point.9 ( *PT7 - wsp *MASTER -  )": stored without definition
  Point11 "Point.10 ( *PT8 - wsp *MASTER -  )": stored without definition
  Point12 "Point.11 ( *PT9 - wsp *MASTER -  )": stored without definition
  Point13 "Point.12 ( *PT10 - wsp *MASTER -  )": stored without definition
  Point14 "Point.13 ( *PT11 - wsp *MASTER -  )": stored without definition
  Point15 "Point.14 ( *PT12 - wsp *MASTER -  )": stored without definition
  Point16 "Point.15 ( *PT13 - wsp *MASTER -  )": stored without definition
  Point17 "Point.16 ( *PT14 - wsp *MASTER -  )": stored without definition
  Point18 "Point.18 ( *PT17 - wsp *MASTER -  )": stored without definition
  Plane30: type Offset, RefPlane face of Pad1 from Sketch1.L5, Offset 0, reversed
  Plane31: type Angle, RefPlane Plane30, Direction edge [ZX plane of AxisSystem2 | YZ plane of AxisSystem2], Angle 90
  Plane32: type Offset, RefPlane start face of Pocket23, Offset 0
  Line36: type Normal, RefPoint vertex [YZ plane of AxisSystem1 | ZX plane of AxisSystem1 | XY plane of AxisSystem1], RefSkin Plane31, Start 0, End 25.4
  Line37: type Normal, RefPoint vertex [YZ plane of AxisSystem1 | ZX plane of AxisSystem1 | XY plane of AxisSystem1], RefSkin Plane30, Start 0, End 25.4
  Plane33: type 2Lines, Element1 Line36, Element2 Line37
  Plane34: type Normal, Curve edge [face of Pocket19 | face of Pocket12 from Sketch14.L4], RefPoint vertex [face of Pocket19 | face of Pocket12 from Sketch14.L4 | face of Pad1 from Sketch1.L1]
Body1 "MP_3" (main body)
  Pad1: profile Sketch1, direction (0, 0, -1), up to Plane29
  Pocket1: profile Sketch12, direction (0.9912, -0.1324, 0), length 76.2
  Pocket2: profile Sketch10, direction (0.9912, -0.1324, 0), length 76.2
  Pocket3: profile Sketch9, direction (0.9912, -0.1324, 0), length 76.2
  Pocket4: profile Sketch4, direction (0, 0, 1), up to Plane12, opposite side up to Plane27
  Pocket5: profile Sketch2, direction (0, 0, 1), length 76.2
  Pocket6: profile Sketch3, direction (0, 0, 1), length 76.2
  Pocket7: profile Sketch5, direction (0, 0, 1), length 76.2
  Pocket8: profile Sketch6, direction (0, 0, 1), length 76.2
  Pocket9: profile Sketch8, direction (0, 0, 1), length 76.2
  Pad2: profile Sketch11, direction (0, 0, 1), up to Plane11
  Pocket10: profile Sketch7, direction (0, 0, 1), length 76.2
  Pocket11: profile Sketch13, direction (-0.9912, 0.1324, 0), length 25.4, opposite side length 25.4
  Pocket12: profile Sketch14, direction (0, 0, -1), up to Plane28
  Pocket13: profile Sketch15, direction (0, 0, -1), length 25.4
  Pocket14: profile Sketch16, direction (0, 0, -1), length 50.8
  Pocket15: profile Sketch17, direction (-0.9912, 0.1324, 0), length 11.43, opposite side length 12.7
  Pocket16: profile Sketch18, direction (-0.9912, 0.1324, 0), length 50.8
  Pocket17: profile Sketch19, direction (-0.6553, 0.7554, 0), length 12.7, opposite side length 12.7
  Pocket18: profile Sketch20, direction (-0.7554, -0.6553, 0), length 7.62, opposite side length 7.62
  Pocket19: profile Sketch21, direction (0.7554, 0.6553, 0), length 11.6764, opposite side length 2.54
  Pocket20: profile Sketch22, direction (0, 0, -1), up to Plane29
  Pocket21: profile Sketch23, direction (0, 0, 1), up to Plane29
  Pocket22: profile Sketch25, direction (-0.1324, -0.9912, 0), length 76.2, opposite side length 25.4
  Pocket23: profile Sketch26, direction (-0.1324, -0.9912, 0), length 76.2
  Pocket24: profile Sketch27, direction (-0.1324, -0.9912, 0), length 76.2
  Pocket25: profile Sketch24, direction (-0.9912, 0.1324, 0), length 76.2, opposite side length 25.4
  Sketch29 on face of Pocket19, origin (46.8798, -47.0446, 67.3735), H (1, 0, 0), V (0, 1, 0)
    point P1 (0, 0)
    reference projected point E1 (0, 0) from Point10
    coincidence: E1 P1
  Hole1: placed by Sketch29, at (46.8798, -47.0446, 67.3735) direction (0, 0, -1), diameter 4.8514, depth 10
  Sketch30 on face of Pocket19, origin (64.9277, -57.8364, 67.3735), H (1, 0, 0), V (0, 1, 0)
    point P1 (0, 0)
    reference projected point E1 (0, 0) from Point11
    coincidence: E1 P1
  Hole2: placed by Sketch30, at (64.9277, -57.8364, 67.3735) direction (0, 0, -1), diameter 5.6744, depth 10
  Sketch31 on face of Pocket19, origin (47.6938, -76.4952, 67.3735), H (1, 0, 0), V (0, 1, 0)
    point P1 (0, 0)
    reference projected point E1 (0, 0) from Point12
    coincidence: E1 P1
  Hole3: placed by Sketch31, at (47.6938, -76.4952, 67.3735) direction (0, 0, -1), diameter 5.6744, depth 10
  Sketch32 on start face of Pocket9, origin (64.3366, -25.5275, 5.08), H (1, 0, 0), V (0, 1, 0)
    point P1 (0, 0)
    reference projected point E1 (0, 0) from Point9
    coincidence: E1 P1
  Hole4: placed by Sketch32, at (64.3366, -25.5275, 5.08) direction (0, 0, -1), diameter 7.239, through (limit type 6)
  Sketch33 on start face of Pocket5, origin (10.0681, 126.7179, 5.08), H (1, 0, 0), V (0, 1, 0)
    point P1 (0, 0)
    reference projected point E1 (0, 0) from Point14
    coincidence: E1 P1
  Hole5: placed by Sketch33, at (10.0681, 126.7179, 5.08) direction (0, 0, -1), diameter 7.239, through (limit type 6)
  Sketch34 on start face of Pocket8, origin (-25.9063, -32.5804, 6.858), H (1, 0, 0), V (0, 1, 0)
    point P1 (0, 0)
    intersected point E1 (0, 0) from Line26
    coincidence: E1 P1
  Hole6: placed by Sketch34, at (-25.9063, -32.5804, 6.858) direction (0, 0, -1), diameter 7.239, through (limit type 6)
  Sketch35 on face of Pocket25, origin (47.6938, -76.4952, 26.4795), H (1, 0, 0), V (0, 1, 0)
    point P1 (0, 0)
    intersected point E1 (0, 0) from Line33
    coincidence: E1 P1
  Hole7: placed by Sketch35, at (47.6938, -76.4952, 26.4795) direction (0, 0, -1), diameter 3.6068, through (limit type 6)
  Sketch36 on face of Pocket25, origin (64.9277, -57.8364, 26.4795), H (1, 0, 0), V (0, 1, 0)
    point P1 (0, 0)
    intersected point E1 (0, 0) from Line32
    coincidence: E1 P1
  Hole8: placed by Sketch36, at (64.9277, -57.8364, 26.4795) direction (0, 0, -1), diameter 3.6068, through (limit type 6)
  Sketch37 on face of Pocket25, origin (46.8798, -47.0446, 26.4795), H (1, 0, 0), V (0, 1, 0)
    point P1 (0, 0)
    intersected point E1 (0, 0) from Line30
    coincidence: E1 P1
  Hole9: placed by Sketch37, at (46.8798, -47.0446, 26.4795) direction (0, 0, -1), diameter 4.8514, through (limit type 6)
  Sketch38 on start face of Pocket6, origin (6.9294, 37.5937, 67.3735), H (1, 0, 0), V (0, 1, 0)
    point P1 (0, 0)
    intersected point E1 (0, 0) from Line28
    coincidence: E1 P1
  Hole10: placed by Sketch38, at (6.9294, 37.5937, 67.3735) direction (0, 0, -1), diameter 5.6744, through (limit type 6)
  Sketch39 on face of Pocket2 from Sketch10.L2, origin (0, 162.1444, 42.4434), H (1, 0, 0), V (0, 1, 0)
    point P1 (0, 0)
    intersected point E1 (0, 0) from Line23
    coincidence: E1 P1
  Hole11: placed by Sketch39, at (0, 162.1444, 42.4434) direction (0, 0, -1), diameter 7.9502, up to face of Pocket2 from Sketch10.L6
  Sketch40 on face of Pocket1 from Sketch12.L2, origin (0, 162.1444, 59.4614), H (1, 0, 0), V (0, 1, 0)
    point P1 (0, 0)
    intersected point E1 (0, 0) from Line20
    coincidence: E1 P1
  Hole12: placed by Sketch40, at (0, 162.1444, 59.4614) direction (0, 0, -1), diameter 4.8514, depth 37.338
  Sketch41 on face of Pocket1 from Sketch12.L2, origin (-5.3852, 144.8456, 59.4614), H (1, 0, 0), V (0, 1, 0)
    point P1 (0, 0)
    intersected point E1 (0, 0) from Line24
    coincidence: E1 P1
  Hole13: placed by Sketch41, at (-5.3852, 144.8456, 59.4614) direction (0, 0, -1), diameter 3.5916, through (limit type 6)
  Sketch42 on start face of Pocket7, origin (-6.9294, -37.5937, 67.3735), H (1, 0, 0), V (0, 1, 0)
    point P1 (0, 0)
    reference projected point E1 (0, 0) from Point7
    coincidence: E1 P1
  Hole14: placed by Sketch42, at (-6.9294, -37.5937, 67.3735) direction (0, 0, -1), diameter 5.6744, through (limit type 6)
  Body2
    Shaft1: profile Sketch28, axis Line19, angle 360
  Remove1: tool Body2
  Fillet1: radius 1.524, on edge [face of Pocket7 | start face of Pocket7]
  Fillet2: radius 1.524, on edge [face of Pocket8 from Sketch6.L5 | start face of Pocket8]
  Fillet3: radius 1.524, on edge [face of Pocket5 from Sketch2.A3 | start face of Pocket5]
  Fillet4: radius 1.524, on edge [face of Pocket9 from Sketch8.A1 | start face of Pocket9]
  Fillet5: radius 1.524, on edge [face of Pocket6 | start face of Pocket6]
  Fillet6: radius 1.524, on edge [start face of Pocket4 | face of Pocket4 from Sketch4.L2]
  Fillet7: radius 1.524, on edge [face of Pocket21 from Sketch23.L9 | face of Pocket25]; edge [face of Pocket21 from Sketch23.A6 | face of Pocket25]
  Fillet8: radius 1.524, on edge [face of Pocket14 from Sketch16.A5 | face of Pocket18]
  Fillet9: radius 1.524, on edge [face of Pocket14 from Sketch16.A2 | face of Pocket18]
  Fillet10: radius 1.524, on edge [face of Pocket13 from Sketch15.L2 | face of Pocket18]
  Fillet11: radius 1.524, on edge [face of Pocket23 from Sketch26.A2 | start face of Pocket23]
  Fillet12: radius 1.524, on edge [face of Pocket24 from Sketch27.A2 | start face of Pocket24]
  Fillet13: radius 1.524, on edge [face of Pocket25 | face of Pocket25]
  Fillet14: radius 1.524, on edge [face of Pocket25 | face of Pocket25]
  Fillet15: radius 1.524, on edge [face of Pocket10 from Sketch7.L1 | face of Pocket19]
  Fillet16: radius 1.524, on edge [face of Pocket20 from Sketch22.L2 | face of Pocket3]
  Sketch43 on end face of Pad1, origin (-6.1693, 128.659, 0), H (1, 0, 0), V (0, -1, 0)
    point P1 (0, 0)
    reference projected point E1 (0, 0) from Point17
    coincidence: E1 P1
  Hole15: placed by Sketch43, at (-6.1693, 128.659, 0) direction (0, 0, 1), diameter 4.8006, depth 13.3731
  Chamfer1: length 0.635, angle 45, on edge [end face of Pad1 | face of Hole15]
  Fillet17: radius 0.508, on edge [face of Pad2 from Sketch11.L1 | face of Pocket1 from Sketch12.L2]; edge [face of Pad2 from Sketch11.L4 | face of Pocket1 from Sketch12.L2]; edge [face of Pad2 from Sketch11.L3 | face of Pocket1 from Sketch12.L2]
  Chamfer2: length 0.635, angle 45, on edge [face of Hole13 | face of Pocket1 from Sketch12.L2]; edge [end face of Pad1 | face of Hole5]; edge [end face of Pad1 | face of Hole6]; edge [end face of Pad1 | face of Hole4]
